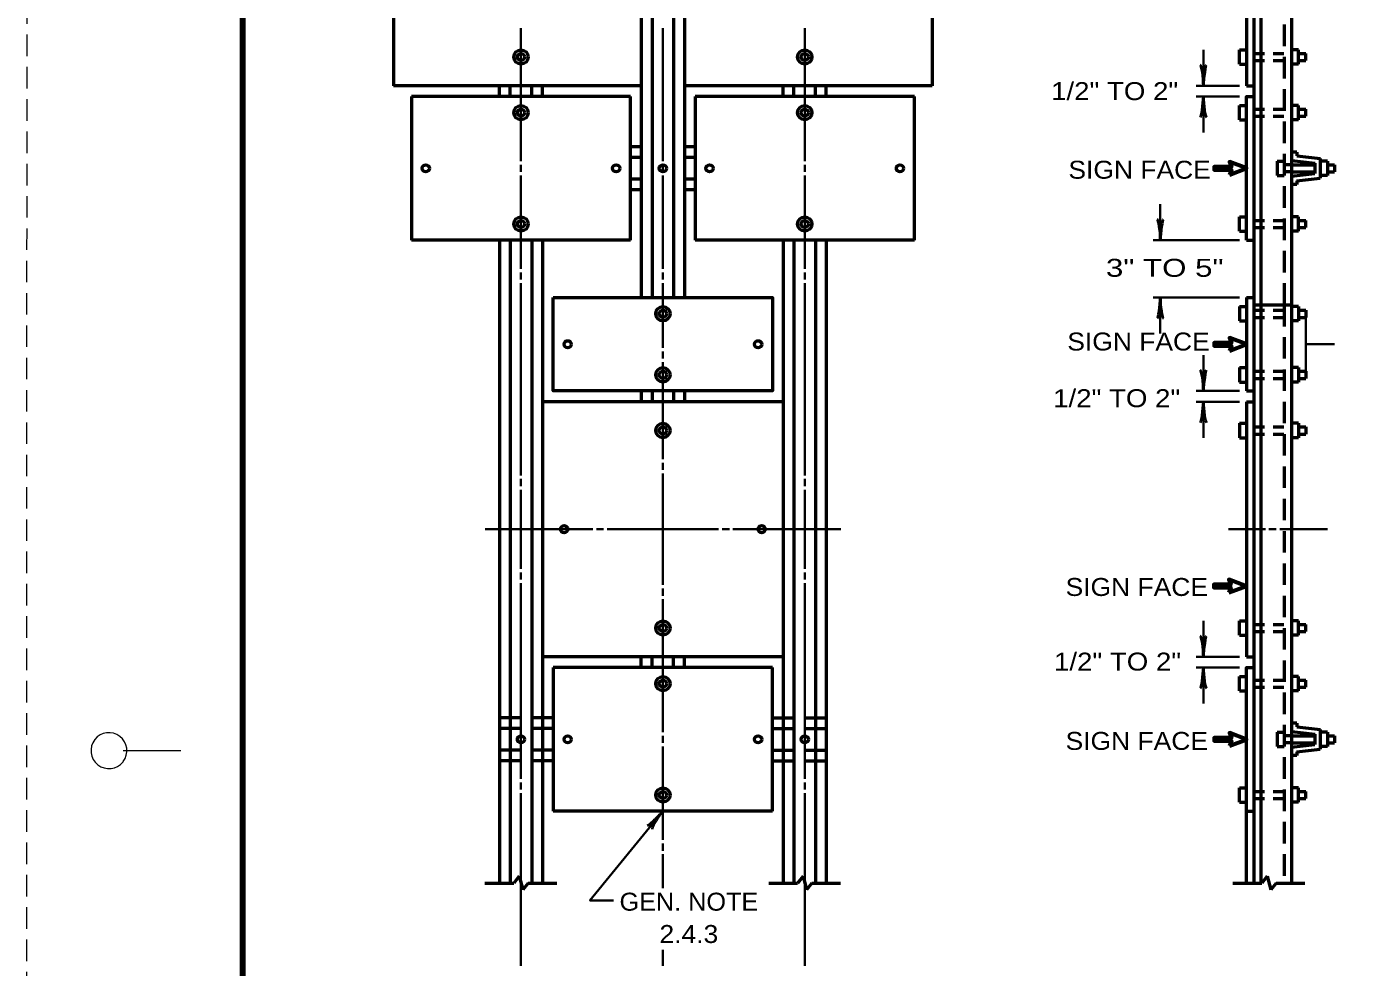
# Model space of a CAD drawing. Extents: x -45 to 635, y -382 to 59.
# Drawn here: x -44.9 to 139.3, y -273.9 to -142.8 of the extents above; entities that cross this region are included whole.
import ezdxf
from ezdxf.enums import TextEntityAlignment as Align

# ---------------------------------------------------------------- set-up
doc = ezdxf.new("R2010")
doc.units = 0
doc.linetypes.add('MEDIUM_DASHED', pattern=[4.5, 3, -1.5])
doc.linetypes.add('SHORT_DASHED', pattern=[2.7, 1.5, -1.2])
doc.layers.add('1', color=7, linetype='Continuous', lineweight=53)
doc.layers.add('61', color=7, linetype='Continuous', lineweight=35)

msp = doc.modelspace()

# ---------------------------------------------------------------- linework, layer by layer
at = {"layer": '1', "linetype": 'MEDIUM_DASHED', "lineweight": 13}
msp.add_line((-44.831, 58.54), (-44.891, -381.5), dxfattribs=at)
at = {"layer": '1'}
for p, q in [((126.922, -102.09), (126.922, -181.59)), ((131.172, -102.09), (131.172, -181.59)), ((6.187, -115.59), (6.187, -151.09)), ((40.687, -115.59), (40.687, -151.09)), ((42.187, -115.59), (42.187, -151.09)), ((45.187, -115.59), (45.187, -151.09)), ((46.687, -115.59), (46.687, -151.09)), ((81.187, -115.59), (81.187, -151.09)), ((124.922, -115.59), (124.922, -151.09)), ((123.922, -148.09), (123.922, -146.09)), ((123.922, -146.09), (124.922, -146.09)), ((132.172, -146.09), (131.172, -146.09)), ((132.172, -148.09), (132.172, -146.09)), ((132.172, -146.59), (133.172, -146.59)), ((133.172, -147.59), (133.172, -146.59)), ((123.922, -148.09), (124.922, -148.09)), ((132.172, -148.09), (131.172, -148.09)), ((132.172, -147.59), (133.172, -147.59)), ((40.687, -151.09), (6.187, -151.09)), ((39.187, -152.59), (8.687, -152.59)), ((8.687, -152.59), (8.687, -172.59)), ((20.937, -152.59), (20.937, -151.09)), ((22.437, -152.59), (22.437, -151.09)), ((25.437, -152.59), (25.437, -151.09)), ((26.937, -152.59), (26.937, -151.09)), ((39.187, -172.59), (39.187, -152.59)), ((40.687, -151.09), (40.687, -180.59)), ((42.187, -151.09), (42.187, -180.59)), ((45.187, -151.09), (45.187, -180.59)), ((81.187, -151.09), (46.687, -151.09)), ((46.687, -151.09), (46.687, -180.59)), ((78.687, -152.59), (48.187, -152.59)), ((48.187, -152.59), (48.187, -172.59)), ((60.437, -152.59), (60.437, -151.09)), ((61.937, -152.59), (61.937, -151.09)), ((64.937, -152.59), (64.937, -151.09)), ((66.437, -152.59), (66.437, -151.09)), ((78.687, -172.59), (78.687, -152.59)), ((124.922, -151.09), (125.922, -151.09)), ((123.922, -155.84), (123.922, -153.84)), ((123.922, -153.84), (124.922, -153.84)), ((132.172, -153.84), (131.172, -153.84)), ((132.172, -155.84), (132.172, -153.84)), ((132.172, -154.34), (133.172, -154.34)), ((133.172, -155.34), (133.172, -154.34)), ((123.922, -155.84), (124.922, -155.84)), ((132.172, -155.84), (131.172, -155.84)), ((132.172, -155.34), (133.172, -155.34)), ((40.687, -159.59), (39.187, -159.59)), ((48.187, -159.59), (46.687, -159.59)), ((40.687, -161.09), (39.187, -161.09)), ((48.187, -161.09), (46.687, -161.09)), ((129.172, -161.59), (129.172, -163.59)), ((129.172, -161.59), (130.172, -161.59)), ((131.922, -160.34), (131.172, -160.34)), ((131.172, -161.511), (134.422, -161.872)), ((131.922, -160.34), (131.922, -160.84)), ((131.922, -160.84), (135.172, -161.201)), ((134.422, -161.872), (134.422, -163.308)), ((135.172, -161.201), (135.172, -163.979)), ((136.172, -161.59), (135.172, -161.59)), ((136.172, -161.59), (136.172, -163.59)), ((129.172, -163.59), (130.172, -163.59)), ((131.172, -162.09), (134.422, -162.09)), ((131.172, -163.09), (134.422, -163.09)), ((131.172, -163.669), (134.422, -163.308)), ((136.172, -163.59), (135.172, -163.59)), ((136.172, -162.09), (137.172, -162.09)), ((136.172, -163.09), (137.172, -163.09)), ((137.172, -162.09), (137.172, -163.09)), ((40.687, -164.09), (39.187, -164.09)), ((40.687, -165.59), (39.187, -165.59)), ((48.187, -164.09), (46.687, -164.09)), ((48.187, -165.59), (46.687, -165.59)), ((131.922, -164.84), (131.172, -164.84)), ((131.922, -164.34), (135.172, -163.979)), ((131.922, -164.34), (131.922, -164.84)), ((123.922, -171.34), (123.922, -169.34)), ((123.922, -169.34), (124.922, -169.34)), ((132.172, -169.34), (131.172, -169.34)), ((132.172, -171.34), (132.172, -169.34)), ((132.172, -169.84), (133.172, -169.84)), ((132.172, -170.84), (133.172, -170.84)), ((133.172, -170.84), (133.172, -169.84)), ((39.187, -172.59), (8.687, -172.59)), ((20.937, -172.59), (20.937, -262.09)), ((22.437, -172.59), (22.437, -262.09)), ((25.437, -172.59), (25.437, -262.09)), ((26.937, -172.59), (26.937, -262.09)), ((78.687, -172.59), (48.187, -172.59)), ((60.437, -172.59), (60.437, -262.09)), ((61.937, -172.59), (61.937, -262.09)), ((64.937, -172.59), (64.937, -262.09)), ((66.437, -172.59), (66.437, -262.09)), ((123.922, -171.34), (124.922, -171.34)), ((124.922, -172.59), (125.922, -172.59)), ((132.172, -171.34), (131.172, -171.34)), ((123.922, -181.84), (123.922, -183.84)), ((123.922, -181.84), (124.922, -181.84)), ((124.922, -180.59), (124.922, -193.59)), ((124.922, -180.59), (125.922, -180.59)), ((125.922, -181.59), (131.172, -181.59)), ((126.922, -181.59), (126.922, -262.11)), ((131.172, -181.59), (131.172, -262.11)), ((132.172, -181.84), (131.172, -181.84)), ((132.172, -181.84), (132.172, -183.84)), ((123.922, -183.84), (124.922, -183.84)), ((132.172, -183.84), (131.172, -183.84)), ((132.172, -182.34), (133.172, -182.34)), ((132.172, -183.34), (133.172, -183.34)), ((133.172, -182.34), (133.172, -183.34)), ((123.922, -190.34), (123.922, -192.34)), ((123.922, -190.34), (124.922, -190.34)), ((132.172, -190.34), (131.172, -190.34)), ((132.172, -190.34), (132.172, -192.34)), ((132.172, -190.84), (133.172, -190.84)), ((133.172, -190.84), (133.172, -191.84)), ((123.922, -192.34), (124.922, -192.34)), ((132.172, -192.34), (131.172, -192.34)), ((132.172, -191.84), (133.172, -191.84)), ((60.437, -195.09), (26.937, -195.09)), ((40.687, -193.59), (40.687, -195.09)), ((42.187, -193.59), (42.187, -195.09)), ((45.187, -193.59), (45.187, -195.09)), ((46.687, -193.59), (46.687, -195.09)), ((124.922, -193.59), (125.922, -193.59)), ((124.922, -195.09), (124.922, -230.59)), ((124.922, -195.09), (125.922, -195.09)), ((123.922, -198.09), (123.922, -200.09)), ((123.922, -198.09), (124.922, -198.09)), ((132.172, -198.09), (131.172, -198.09)), ((132.172, -198.09), (132.172, -200.09)), ((132.172, -198.59), (133.172, -198.59)), ((133.172, -198.59), (133.172, -199.59)), ((123.922, -200.09), (124.922, -200.09)), ((132.172, -200.09), (131.172, -200.09)), ((132.172, -199.59), (133.172, -199.59)), ((123.922, -227.59), (123.922, -225.59)), ((123.922, -225.59), (124.922, -225.59)), ((132.172, -225.59), (131.172, -225.59)), ((132.172, -227.59), (132.172, -225.59)), ((132.172, -226.09), (133.172, -226.09)), ((133.172, -227.09), (133.172, -226.09)), ((123.922, -227.59), (124.922, -227.59)), ((132.172, -227.59), (131.172, -227.59)), ((132.172, -227.09), (133.172, -227.09)), ((60.437, -230.59), (26.937, -230.59)), ((40.687, -232.09), (40.687, -230.59)), ((42.187, -232.09), (42.187, -230.59)), ((45.187, -232.09), (45.187, -230.59)), ((46.687, -232.09), (46.687, -230.59)), ((124.922, -230.59), (125.922, -230.59)), ((58.937, -232.09), (28.437, -232.09)), ((28.437, -232.09), (28.437, -252.09)), ((58.937, -252.09), (58.937, -232.09)), ((123.922, -235.34), (123.922, -233.34)), ((123.922, -233.34), (124.922, -233.34)), ((132.172, -233.34), (131.172, -233.34)), ((132.172, -235.34), (132.172, -233.34)), ((132.172, -233.84), (133.172, -233.84)), ((133.172, -234.84), (133.172, -233.84)), ((123.922, -235.34), (124.922, -235.34)), ((132.172, -235.34), (131.172, -235.34)), ((132.172, -234.84), (133.172, -234.84)), ((129.172, -241.09), (129.172, -243.09)), ((129.172, -241.09), (130.172, -241.09)), ((131.922, -239.84), (131.172, -239.84)), ((131.172, -241.011), (134.422, -241.372)), ((131.922, -239.84), (131.922, -240.34)), ((131.922, -240.34), (135.172, -240.701)), ((135.172, -240.701), (135.172, -243.479)), ((136.172, -241.09), (135.172, -241.09)), ((136.172, -241.09), (136.172, -243.09)), ((131.172, -241.59), (134.422, -241.59)), ((131.172, -242.59), (134.422, -242.59)), ((131.172, -243.169), (134.422, -242.808)), ((134.422, -241.372), (134.422, -242.808)), ((136.172, -241.59), (137.172, -241.59)), ((136.172, -242.59), (137.172, -242.59)), ((137.172, -241.59), (137.172, -242.59)), ((129.172, -243.09), (130.172, -243.09)), ((131.922, -244.34), (131.172, -244.34)), ((131.922, -243.84), (135.172, -243.479)), ((131.922, -243.84), (131.922, -244.34)), ((136.172, -243.09), (135.172, -243.09)), ((123.922, -250.84), (123.922, -248.84)), ((123.922, -248.84), (124.922, -248.84)), ((132.172, -248.84), (131.172, -248.84)), ((132.172, -250.84), (132.172, -248.84)), ((132.172, -249.34), (133.172, -249.34)), ((132.172, -250.34), (133.172, -250.34)), ((133.172, -250.34), (133.172, -249.34)), ((58.937, -252.09), (28.437, -252.09)), ((123.922, -250.84), (124.922, -250.84)), ((124.922, -252.09), (125.922, -252.09)), ((132.172, -250.84), (131.172, -250.84)), ((23.699, -261.137), (22.921, -262.11)), ((23.699, -261.137), (24.175, -263.043)), ((63.199, -261.137), (62.421, -262.11)), ((63.199, -261.137), (63.675, -263.043)), ((127.809, -261.157), (127.031, -262.131)), ((127.809, -261.157), (128.285, -263.063)), ((18.921, -262.11), (22.921, -262.11)), ((24.921, -262.11), (24.175, -263.043)), ((24.921, -262.11), (28.921, -262.11)), ((58.421, -262.11), (62.421, -262.11)), ((64.421, -262.11), (63.675, -263.043)), ((64.421, -262.11), (68.421, -262.11)), ((123.031, -262.131), (127.031, -262.131)), ((129.031, -262.131), (128.285, -263.063)), ((129.031, -262.131), (133.031, -262.131))]:
    msp.add_line(p, q, dxfattribs=at)
at = {"layer": '1', "linetype": 'MEDIUM_DASHED'}
for p, q in [((130.172, -102.09), (130.172, -181.59)), ((130.172, -181.59), (130.172, -262.11)), ((28.437, -239.09), (20.937, -239.09)), ((58.937, -239.09), (66.437, -239.09)), ((28.437, -240.59), (20.937, -240.59)), ((58.937, -240.59), (66.437, -240.59)), ((28.437, -243.59), (20.937, -243.59)), ((58.937, -243.59), (66.437, -243.59)), ((28.437, -245.09), (20.937, -245.09)), ((58.937, -245.09), (66.437, -245.09))]:
    msp.add_line(p, q, dxfattribs=at)
at = {"layer": '1', "lineweight": 35}
for p, q in [((23.937, -143.09), (23.937, -161.59)), ((43.687, -143.09), (43.687, -161.59)), ((63.437, -143.09), (63.437, -161.59)), ((118.922, -151.09), (118.922, -146.09)), ((123.922, -151.09), (117.922, -151.09)), ((123.922, -152.59), (117.922, -152.59)), ((118.922, -157.59), (118.922, -152.59)), ((23.937, -162.09), (23.937, -163.09)), ((23.937, -163.59), (23.937, -176.59)), ((43.687, -162.09), (43.687, -163.09)), ((43.687, -163.59), (43.687, -176.59)), ((63.437, -162.09), (63.437, -163.09)), ((63.437, -163.59), (63.437, -176.59)), ((112.922, -172.59), (112.922, -167.59)), ((123.922, -172.59), (111.922, -172.59)), ((23.937, -177.09), (23.937, -178.09)), ((23.937, -178.59), (23.937, -182.59)), ((43.687, -177.09), (43.687, -178.09)), ((43.687, -178.59), (43.687, -180.59)), ((63.437, -177.09), (63.437, -178.09)), ((63.437, -178.59), (63.437, -205.34)), ((43.687, -180.59), (43.687, -187.59)), ((123.922, -180.59), (111.922, -180.59)), ((112.922, -185.59), (112.922, -180.59)), ((23.937, -182.59), (23.937, -205.34)), ((133.172, -183.34), (133.172, -190.84)), ((137.172, -187.09), (133.172, -187.09)), ((43.687, -188.09), (43.687, -189.09)), ((43.687, -189.59), (43.687, -203.09)), ((118.922, -193.59), (118.922, -188.59)), ((123.922, -193.59), (117.922, -193.59)), ((123.922, -195.09), (117.922, -195.09)), ((118.922, -200.09), (118.922, -195.09)), ((43.687, -203.59), (43.687, -204.59)), ((23.937, -205.84), (23.937, -206.84)), ((43.687, -205.09), (43.687, -220.59)), ((63.437, -205.84), (63.437, -206.84)), ((23.937, -207.34), (23.937, -218.34)), ((63.437, -207.34), (63.437, -218.34)), ((18.937, -212.84), (33.937, -212.84)), ((34.437, -212.84), (35.437, -212.84)), ((35.937, -212.84), (51.437, -212.84)), ((51.937, -212.84), (52.937, -212.84)), ((53.437, -212.84), (68.437, -212.84)), ((122.422, -212.84), (127.547, -212.84)), ((128.047, -212.84), (129.047, -212.84)), ((129.547, -212.84), (136.172, -212.84)), ((23.937, -218.84), (23.937, -219.84)), ((63.437, -218.84), (63.437, -219.84)), ((23.937, -220.34), (23.937, -247.59)), ((63.437, -220.34), (63.437, -247.59)), ((43.687, -221.09), (43.687, -222.09)), ((43.687, -222.59), (43.687, -241.09)), ((118.922, -230.59), (118.922, -225.59)), ((123.922, -230.59), (117.922, -230.59)), ((123.922, -232.09), (117.922, -232.09)), ((118.922, -237.09), (118.922, -232.09)), ((43.687, -241.59), (43.687, -242.59)), ((43.687, -243.09), (43.687, -256.09)), ((23.937, -248.09), (23.937, -249.09)), ((63.437, -248.09), (63.437, -249.09)), ((23.937, -249.59), (23.937, -273.61)), ((63.437, -249.59), (63.437, -273.61)), ((43.687, -256.59), (43.687, -257.59)), ((43.687, -258.09), (43.687, -262.819)), ((43.687, -271.414), (43.687, -273.61))]:
    msp.add_line(p, q, dxfattribs=at)
at = {"layer": '1', "linetype": 'SHORT_DASHED'}
for p, q in [((125.922, -146.59), (131.172, -146.59)), ((125.922, -147.59), (131.172, -147.59)), ((125.922, -154.34), (131.172, -154.34)), ((125.922, -155.34), (131.172, -155.34)), ((131.172, -162.09), (130.172, -162.09)), ((131.172, -163.09), (130.172, -163.09)), ((125.922, -169.84), (131.172, -169.84)), ((125.922, -170.84), (131.172, -170.84)), ((125.922, -182.34), (131.172, -182.34)), ((125.922, -183.34), (131.172, -183.34)), ((125.922, -190.84), (131.172, -190.84)), ((125.922, -191.84), (131.172, -191.84)), ((125.922, -198.59), (131.172, -198.59)), ((125.922, -199.59), (131.172, -199.59)), ((125.922, -226.09), (131.172, -226.09)), ((125.922, -227.09), (131.172, -227.09)), ((125.922, -233.84), (131.172, -233.84)), ((125.922, -234.84), (131.172, -234.84)), ((131.172, -241.59), (130.172, -241.59)), ((131.172, -242.59), (130.172, -242.59)), ((125.922, -249.34), (131.172, -249.34)), ((125.922, -250.34), (131.172, -250.34))]:
    msp.add_line(p, q, dxfattribs=at)
at = {"layer": '1'}
for points in [[(125.922, -101.09), (125.922, -115.59), (125.922, -180.59)], [(124.922, -172.59), (124.922, -152.59), (125.922, -152.59)], [(125.922, -180.59), (125.922, -195.09), (125.922, -262.09)], [(124.922, -262.11), (124.922, -232.09), (125.922, -232.09)]]:
    msp.add_lwpolyline(points, dxfattribs=at)
at = {"layer": '1', "lineweight": 60}
for points in [[(122.537, -163.49), (124.922, -162.59), (122.537, -161.69), (122.807, -162.365), (120.422, -162.365), (120.422, -162.815), (122.807, -162.815)], [(122.537, -187.99), (124.922, -187.09), (122.537, -186.19), (122.807, -186.865), (120.422, -186.865), (120.422, -187.315), (122.807, -187.315)], [(122.469, -221.641), (124.854, -220.742), (122.469, -219.841), (122.739, -220.516), (120.354, -220.516), (120.354, -220.966), (122.739, -220.966)], [(122.537, -242.99), (124.922, -242.09), (122.537, -241.19), (122.807, -241.865), (120.422, -241.865), (120.422, -242.315), (122.807, -242.315)]]:
    msp.add_lwpolyline(points, close=True, dxfattribs=at)
at = {"layer": '1'}
msp.add_lwpolyline([(28.437, -180.59), (58.937, -180.59), (58.937, -193.59), (28.437, -193.59)], close=True, dxfattribs=at)
at = {"layer": '1', "lineweight": 35}
msp.add_lwpolyline([(43.687, -252.09), (33.533, -264.511), (36.829, -264.511)], dxfattribs=at)
at = {"layer": '1'}
for centre, radius in [((23.937, -147.09), 1), ((23.937, -147.09), 0.5), ((63.437, -147.09), 1), ((63.437, -147.09), 0.5), ((23.937, -154.84), 1), ((23.937, -154.84), 0.5), ((63.437, -154.84), 1), ((63.437, -154.84), 0.5), ((10.687, -162.59), 0.5), ((37.187, -162.59), 0.5), ((43.687, -162.59), 0.5), ((50.187, -162.59), 0.5), ((76.687, -162.59), 0.5), ((23.937, -170.34), 1), ((63.437, -170.34), 1), ((23.937, -170.34), 0.5), ((63.437, -170.34), 0.5), ((43.687, -182.84), 1), ((43.687, -182.84), 0.5), ((30.437, -187.09), 0.5), ((56.937, -187.09), 0.5), ((43.687, -191.34), 1), ((43.687, -191.34), 0.5), ((43.687, -199.09), 1), ((43.687, -199.09), 0.5), ((29.937, -212.84), 0.5), ((57.437, -212.84), 0.5), ((43.687, -226.59), 1), ((43.687, -226.59), 0.5), ((43.687, -234.34), 1), ((43.687, -234.34), 0.5), ((23.937, -242.09), 0.5), ((30.437, -242.09), 0.5), ((56.937, -242.09), 0.5), ((63.437, -242.09), 0.5), ((43.687, -249.84), 1), ((43.687, -249.84), 0.5)]:
    msp.add_circle(centre, radius, dxfattribs=at)
at = {"layer": '1', "lineweight": 40}
for centre, major_axis, ratio, start_param, end_param in [((118.646, -149.999), (0.156, -1.786), 0.122415, 0.8963533, 3.1415927), ((118.646, -149.999), (0.156, -1.786), 0.122415, 0.8963533, 3.1415927), ((119.134, -149.969), (-0.176, -1.756), 0.07063, 3.1407148, 5.41811), ((119.134, -149.969), (-0.176, -1.756), 0.07063, 3.1407148, 5.41811), ((118.71, -153.71), (0.176, 1.756), 0.07063, 3.1407148, 5.41811), ((119.198, -153.681), (-0.156, 1.786), 0.122415, 0.8963533, 3.1415927), ((112.646, -171.499), (0.156, -1.786), 0.122415, 0.8963533, 3.1415927), ((112.646, -171.499), (0.156, -1.786), 0.122415, 0.8963533, 3.1415927), ((113.134, -171.469), (-0.176, -1.756), 0.07063, 3.1407148, 5.41811), ((113.134, -171.469), (-0.176, -1.756), 0.07063, 3.1407148, 5.41811), ((112.71, -181.71), (0.176, 1.756), 0.07063, 3.1407148, 5.41811), ((112.71, -181.71), (0.176, 1.756), 0.07063, 3.1407148, 5.41811), ((113.198, -181.681), (-0.156, 1.786), 0.122415, 0.8963533, 3.1415927), ((113.198, -181.681), (-0.156, 1.786), 0.122415, 0.8963533, 3.1415927), ((118.646, -192.499), (0.156, -1.786), 0.122415, 0.8963533, 3.1415927), ((118.646, -192.499), (0.156, -1.786), 0.122415, 0.8963533, 3.1415927), ((119.134, -192.469), (-0.176, -1.756), 0.07063, 3.1407148, 5.41811), ((119.134, -192.469), (-0.176, -1.756), 0.07063, 3.1407148, 5.41811), ((118.71, -196.21), (0.176, 1.756), 0.07063, 3.1407148, 5.41811), ((119.198, -196.181), (-0.156, 1.786), 0.122415, 0.8963533, 3.1415927), ((118.646, -229.499), (0.156, -1.786), 0.122415, 0.8963533, 3.1415927), ((118.646, -229.499), (0.156, -1.786), 0.122415, 0.8963533, 3.1415927), ((119.134, -229.469), (-0.176, -1.756), 0.07063, 3.1407148, 5.41811), ((119.134, -229.469), (-0.176, -1.756), 0.07063, 3.1407148, 5.41811), ((118.71, -233.21), (0.176, 1.756), 0.07063, 3.1407148, 5.41811), ((118.71, -233.21), (0.176, 1.756), 0.07063, 3.1407148, 5.41811), ((119.198, -233.181), (-0.156, 1.786), 0.122415, 0.8963533, 3.1415927), ((119.198, -233.181), (-0.156, 1.786), 0.122415, 0.8963533, 3.1415927), ((42.814, -252.823), (1.248, 1.249), 0.07063, 3.1407148, 5.41811), ((43.21, -253.109), (1.009, 1.481), 0.122415, 0.8963533, 3.1415927)]:
    msp.add_ellipse(centre, major_axis=major_axis, ratio=ratio, start_param=start_param, end_param=end_param, dxfattribs=at)
at = {"layer": '61', "lineweight": 13}
msp.add_line((-31.411, -243.64), (-23.411, -243.64), dxfattribs=at)
at = {"layer": '61', "lineweight": 158}
msp.add_lwpolyline([(624.209, 48.54), (-14.831, 48.54), (-14.831, -371.48)], dxfattribs=at)
at = {"layer": '61', "lineweight": 13}
msp.add_arc((-33.413, -243.659), 2.5, 322.67175, 321.71615, dxfattribs=at)

# ---------------------------------------------------------------- texts
at = {"layer": '1'}
for s, width, p in [('1/2" TO 2"', 1.15, (106.568, -153.093)), ('SIGN FACE', 1.1, (110.041, -164.039)), ('3" TO 5"', 1.3, (113.54, -177.694)), ('SIGN FACE', 1.1, (109.886, -187.956)), ('1/2" TO 2"', 1.15, (106.853, -195.844)), ('SIGN FACE', 1.1, (109.648, -222.126)), ('1/2" TO 2"', 1.15, (106.972, -232.515)), ('SIGN FACE', 1.1, (109.648, -243.557)), ('GEN. NOTE', 1.05, (47.306, -265.94)), ('2.4.3', 1.1, (47.306, -270.44))]:
    msp.add_text(s, height=2.5, dxfattribs=dict(at, width=width)).set_placement(p, align=Align.CENTER)

doc.saveas('drawing.dxf')
